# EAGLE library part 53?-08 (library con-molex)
CONNECTOR wire to board 1.25 mm (.049 inch) pitch header
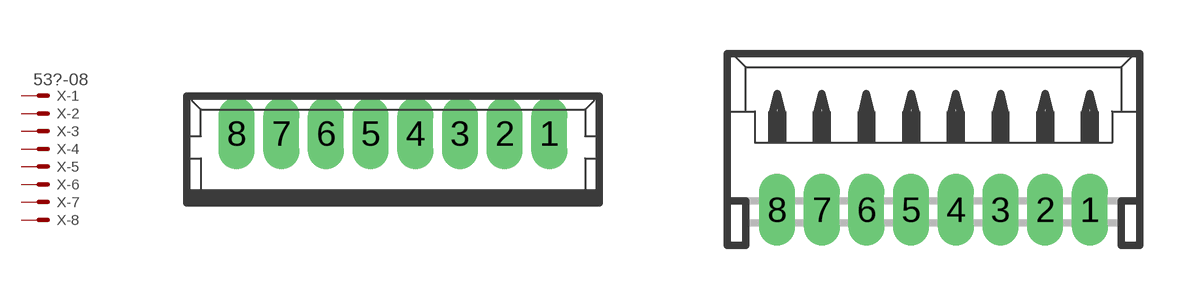
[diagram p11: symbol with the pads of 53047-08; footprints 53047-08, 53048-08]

Designator prefix X; gates -1=MV -2=M -3=M -4=M -5=M -6=M -7=M -8=M

## 53047-08 (MPN: 53047-0810; OC_FARNELL: 1012258; OC_NEWARK: 98K9826)  [53047-08]
1  -1:S  pas
2  -2:S  pas
3  -3:S  pas
4  -4:S  pas
5  -5:S  pas
6  -6:S  pas
7  -7:S  pas
8  -8:S  pas

## 53048-08 (MF: WALDOM/MOLEX; MPN: 53048-0810; OC_FARNELL: 9733094; OC_NEWARK: 38C9913)  [53048-08]
Pads as for 53047-08

## 53261-08 (OC_FARNELL: 1125376; OC_NEWARK: unknown)  [53261-08]
Pads as for 53047-08

## 53398-08 (OC_FARNELL: 1125371; OC_NEWARK: unknown)  [53398-08]
Pads as for 53047-08

## Footprint 53047-08 (pad centres in mm)
CONNECTOR wire to board 1.25 mm (.049 inch) pitch header straight Sourcxe: http://www.molex.com/pdm_docs/sd/530470210_sd.pdf
drill 0.5 pad 0.698 long: 1 4.375,0.45; 2 3.125,0.45; 3 1.875,0.45; 4 0.625,0.45; 5 -0.625,0.45; 6 -1.875,0.45; 7 -3.125,0.45; 8 -4.375,0.45

## Footprint 53048-08 (pad centres in mm)
CONNECTOR wire to board 1.25 mm (.049 inch) pitch header right angle
drill 0.5 pad 0.698 long: 1 4.375,-1.25; 2 3.125,-1.25; 3 1.875,-1.25; 4 0.625,-1.25; 5 -0.625,-1.25; 6 -1.875,-1.25; 7 -3.125,-1.25; 8 -4.375,-1.25

## Footprint 53261-08 (pad centres in mm)
CONNECTOR wire to board 1.25 mm (.049 inch) pitch header SMT right angle
smd 0.8 x 2: 1 4.375,-2.5; 2 3.125,-2.5; 3 1.875,-2.5; 4 0.625,-2.5; 5 -0.625,-2.5; 6 -1.875,-2.5; 7 -3.125,-2.5; 8 -4.375,-2.5
smd 2.1 x 3: S1 6.875,0.625; S2 -6.875,0.625

## Footprint 53398-08 (pad centres in mm)
CONNECTOR wire to board 1.25 mm (.049 inch) pitch header SMT straight
smd 0.8 x 1.8: 1 4.375,-2.5; 2 3.125,-2.5; 3 1.875,-2.5; 4 0.625,-2.5; 5 -0.625,-2.5; 6 -1.875,-2.5; 7 -3.125,-2.5; 8 -4.375,-2.5
smd 2.1 x 3: S1 6.875,0.625; S2 -6.875,0.625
